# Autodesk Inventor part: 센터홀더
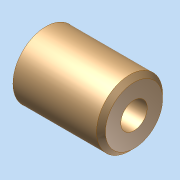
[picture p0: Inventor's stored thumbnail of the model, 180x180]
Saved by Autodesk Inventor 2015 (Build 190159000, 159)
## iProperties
Created: 2026-09
Part Number: 센터홀더
Material: 일반
Document SubType Name: Modeling
Designer: SCD-A06
Density: 1 g/cm^3
Appearance: 기본값
Author: jhkim
Creation Date: 2026-08-27
Sending System: Autodesk Inventor 2027
Preprocessor: ST-DEVELOPER v20.1
Author: SCD-A06
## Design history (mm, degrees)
node "센터홀더1"
node "솔리드1"
node "기준1"
